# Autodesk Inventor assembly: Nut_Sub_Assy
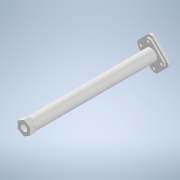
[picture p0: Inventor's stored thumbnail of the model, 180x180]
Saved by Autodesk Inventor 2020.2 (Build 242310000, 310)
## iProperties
Created: 2019-12
Part Number: Nut_Sub_Assy
Document SubType Name: Assembly
Designer: Patrick Everitt
Author: Patrick Everitt
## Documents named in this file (4)
- C:\Users\Patrick Everitt\Documents\Inventor\Fire_Vise\Nut_Sub_Assy.iam
- C:\Users\Patrick Everitt\Documents\Inventor\Fire_Vise\Rear_Cover.ipt
- C:\Users\Patrick Everitt\Documents\Inventor\Fire_Vise\Nut_Tubr.ipt
- C:\Users\Patrick Everitt\Documents\Inventor\Fire_Vise\Modified_Acme_Nut.ipt
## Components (3 placed, 3 different names)
1. Rear_Cover:1 — Mate:3, Mate:4
2. Nut_Tubr:1 — Mate:1, Mate:2, Mate:3, Mate:4
3. Modified_Acme_Nut:1 — Mate:1, Mate:2
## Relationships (4: Mate 4)
- Mate:1: Nut_Tubr:1 ↔ Modified_Acme_Nut:1
- Mate:2: Nut_Tubr:1 ↔ Modified_Acme_Nut:1
- Mate:3: Rear_Cover:1 ↔ Nut_Tubr:1
- Mate:4: Rear_Cover:1 ↔ Nut_Tubr:1
